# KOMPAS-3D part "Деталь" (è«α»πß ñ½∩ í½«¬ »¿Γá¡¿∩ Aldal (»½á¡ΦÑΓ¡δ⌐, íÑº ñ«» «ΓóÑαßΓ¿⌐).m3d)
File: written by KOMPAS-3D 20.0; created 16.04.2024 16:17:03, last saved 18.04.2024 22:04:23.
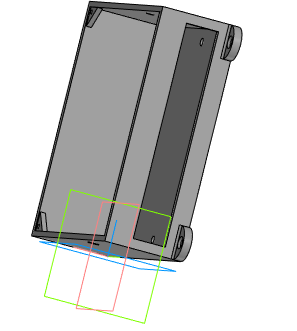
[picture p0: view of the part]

Document properties: Полное имя файла: D:\Soft 4 pads\Чертежи корпусов и т.д\Корпус для блок питания Aldal (планшетный, без доп отверстий).m3d

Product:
- Part/product: Деталь
    Масса: 0.520475

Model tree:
1. Эскиз:1
2. Элемент выдавливания:1
     Расстояние 1 = 38
3. Эскиз:2  (with: Элемент выдавливания:1)
4. Элемент выдавливания:2
     Расстояние 2 = 35
5. Эскиз:3  (with: Элемент выдавливания:1)
6. Элемент выдавливания:3
     Расстояние 2 = 4
7. Скругление:1  (with: Элемент выдавливания:3)
     Радиус = 1
8. Скругление:2  (with: Элемент выдавливания:3)
     Радиус = 1
9. Скругление:3  (with: Элемент выдавливания:3)
     Радиус = 1
10. Скругление:4  (with: Элемент выдавливания:3)
     Радиус = 1
11. Эскиз:4  (with: Элемент выдавливания:1, Элемент выдавливания:3)
12. Элемент выдавливания:4
     Расстояние 2 = 10
13. Скругление:5  (with: Элемент выдавливания:4)
     Радиус = 1
14. Скругление:6  (with: Элемент выдавливания:4)
     Радиус = 1
15. Скругление:7  (with: Элемент выдавливания:4)
     Радиус = 1
16. Скругление:8  (with: Элемент выдавливания:4)
     Радиус = 1
17. Эскиз:5  (with: Элемент выдавливания:2)
18. Элемент выдавливания:5
     Расстояние 2 = 10
19. Скругление:9  (with: Элемент выдавливания:5)
     Радиус = 1
20. Скругление:10  (with: Элемент выдавливания:5)
     Радиус = 1
21. Скругление:11  (with: Элемент выдавливания:5)
     Радиус = 1
22. Скругление:12  (with: Элемент выдавливания:5)
     Радиус = 1
23. Эскиз:6  (with: Элемент выдавливания:2)
24. Элемент выдавливания:6
     Расстояние 2 = 10
25. Эскиз:8  (with: Элемент выдавливания:1, Элемент выдавливания:2)
26. Элемент выдавливания:8
     Расстояние 2 = 3
27. Эскиз:9  (with: Элемент выдавливания:1, Элемент выдавливания:2)
28. Элемент выдавливания:9
     Расстояние 2 = 0.5
29. Эскиз:10  (with: Элемент выдавливания:9)
30. Элемент выдавливания:10
     Расстояние 2 = 10
31. Эскиз:11  (with: Элемент выдавливания:9)
32. Элемент выдавливания:11
     Расстояние 2 = 10
33. Эскиз:12  (with: Элемент выдавливания:9)
34. Элемент выдавливания:12
     Расстояние 2 = 10
35. Эскиз:13  (with: Элемент выдавливания:9)
36. Элемент выдавливания:13
     Расстояние 2 = 10
37. Эскиз:14  (with: Элемент выдавливания:2)
38. Элемент выдавливания:14
     Расстояние 1 = 110; Расстояние 2 = 5
39. Скругление:21  (with: Элемент выдавливания:14)
     Радиус = 1
40. Скругление:22  (with: Элемент выдавливания:14)
     Радиус = 1
41. Эскиз:15  (with: Элемент выдавливания:2, Элемент выдавливания:14)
